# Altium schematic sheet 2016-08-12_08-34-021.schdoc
size 217 x 160 mm; SheetNumber: 1; SheetTotal: 1
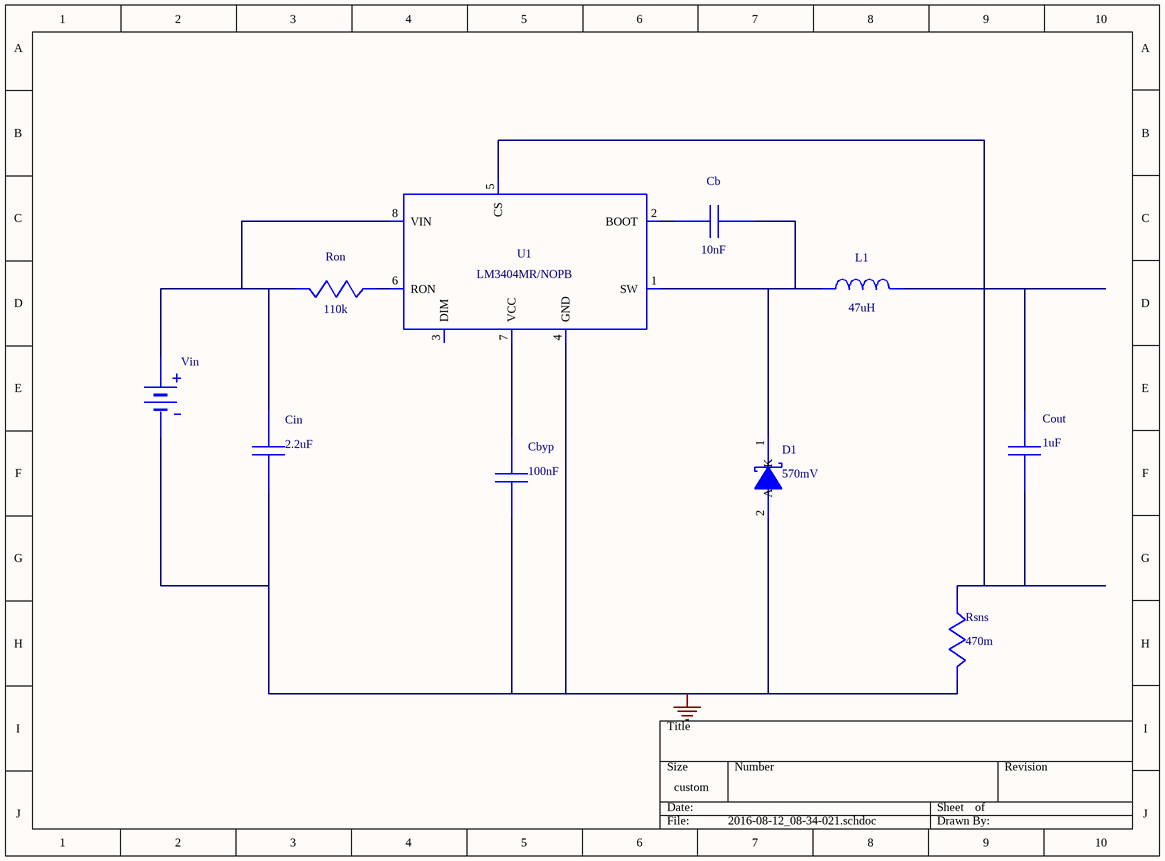
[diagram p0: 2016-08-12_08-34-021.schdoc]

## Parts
Cb  value 10nF  (hidden comment: GRM188R71E103KA01D)
Cbyp  value 100nF  (hidden comment: GRM188R71E104KA01D)
Cin  value 2.2uF  (hidden comment: GRM31CR71H225KA88L)
Cout  value 1uF  (hidden comment: C1608X7R1H472K)
D1  value 570mV  (hidden comment: PMEG6010CEH,115)
L1  value 47uH  (hidden comment: VLP8040T-470M)
Ron  value 110k  (hidden comment: ERJ-6ENF1103V)
Rsns  value 470m  (hidden comment: ERJ-6RQFR47V)
U1  LM3404MR/NOPB
Vin  WB_BATTERY  (value not drawn)

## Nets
0: Cbyp.2 Cin.2 D1.2(A) Rsns.1 U1.4(GND) U1.9(DAP) Vin.2(-)
NetCb_1: Cb.1 U1.2(BOOT)
NetCb_2: Cb.2 D1.1(K) L1.1 U1.1(SW)
NetCbyp_1: Cbyp.1 U1.7(VCC)
NetCin_1: Cin.1 Ron.1 U1.8(VIN) Vin.1(+)
NetCout_1: Cout.1 L1.2
NetCout_2: Cout.2 Rsns.2 U1.5(CS)
NetRon_2: Ron.2 U1.6(RON)

Not connected (* = marked no-connect by the designer): U1 3(DIM)

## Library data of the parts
Cb = GRM188R71E103KA01D: GRM188R71E103KA0; Manufacturer Name: MuRata
Cbyp = GRM188R71E104KA01D: GRM188R71E104KA0; Manufacturer Name: MuRata
Cin = GRM31CR71H225KA88L: GRM31CR71H225KA8; Manufacturer Name: MuRata
Cout = C1608X7R1H472K: C1608X7R1V105K08; Manufacturer Name: TDK
D1 = PMEG6010CEH,115: Manufacturer Name: NXP Semiconductor
L1 = VLP8040T-470M: Unknown; Manufacturer Name: TDK
Ron = ERJ-6ENF1103V: Manufacturer Name: Panasonic
Rsns = ERJ-6RQFR47V: Manufacturer Name: Panasonic
U1 = LM3404MR/NOPB: Manufacturer Name: Texas Instruments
